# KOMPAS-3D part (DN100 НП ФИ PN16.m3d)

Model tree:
1. Операция без истории:1

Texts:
  DN100 НП ФИ PN16
  133 1 134 1 135 1 136 0 50 1|SPDS|133 1 134 1 135 1 136 0 50 1
  125 1 126 1 127 1 128 0 50 1|SPDS|125 1 126 1 127 1 128 0 50 1
  129 1 130 1 131 1 132 0 50 1|SPDS|129 1 130 1 131 1 132 0 50 1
